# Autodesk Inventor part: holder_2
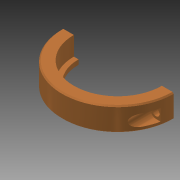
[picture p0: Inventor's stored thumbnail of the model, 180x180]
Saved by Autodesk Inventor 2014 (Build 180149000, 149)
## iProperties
Created: 2002-09
Part Number: holder_2
Document SubType Name: Modeling
Designer: ales
Density: 1 g/cm^3
Material: Generic
Appearance: Copper (Old/Polished)
ProtocolID: P00020918071214950
Protocol: P00020918071214950<@PID>[Object]<@EL>CADDescription=holder_2.ipt<@EL>[GroupMan]<@EL>UseUserDescription=1<@EL>UserDescription=holder_2.ipt<@EL>[Acad]<@EL>SmartPa
Control State: 0
Master: False
Checked Out: False
Shininess: 64.0
Length Units: 11269
Angle Units: 11279
Time Units: 11290
Mass Units: 11283
Length Display Precision: 3
Angle Display Precision: 2
Density: 0.0
Volumn: 0.0
Area: 0.0
PropertySet Name: Model Information
Author: PaulN
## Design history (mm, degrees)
sketch "Sketch1"
  geometry: L1 (24.298, 7.276)-(24.298, -8.724) reference; L2 (24.298, -8.724)-(28.298, -8.724) reference; L3 (28.298, -8.724)-(28.298, -12.724) reference; L4 (28.298, -12.724)-(14.298, -12.724) reference; L5 (14.298, 7.276)-(24.298, 7.276) reference; L6 (14.298, -12.724)-(14.298, 7.276); L7 (95.298, -12.724)-(28.298, -12.724) reference; L8 (61.798, -12.724)-(61.798, 7.654)
  constraints: 4 end point, 2 perpendicular, 1 midpoint, 1 parallel
revolve "Revolution1" sketch "Sketch1" stored, may be unused: angle "d0" = 180 deg
sketch "Sketch2"
  geometry: L1 (14, 20)-(14, 0) reference; L2 (9, 13)-(14, 13); L3 (9, 3)-(14, 3); L4 (4, 20)-(-71, 20) reference; L5 (-33.5, 20)-(-33.5, 4.517); L6 (-81, 0)-(-81, 20) reference; L7 (-76, 13)-(-81, 13); L8 (-76, 3)-(-81, 3); L9 (-81, 13)-(-81, 3); L10 (4, 20)-(14, 20) reference; C1 r 3 at (9, 8); C2 r 3 at (-76, 8); A1 r 5 centre (9, 8) between (9, 13) and (9, 3); A2 r 5 centre (-76, 8) between (-76, 3) and (-76, 13)
  constraints: 12 end point, 6 symmetric about line, 4 centre point, 4 point on circle, 2 coincident, 2 perpendicular, 2 point on line, 2 tangent, 1 collinear, 1 midpoint, 1 parallel, 4 other
  dimensions: "d1" = 10 diameter of A1; "d2" = 5 distance from line of L1 A1.centre; "d3" = 6 diameter of C1; "d11" = 12 distance from line of L10 A1.centre
extrude "Extrusion1" cut sketch "Sketch2" stored distance "d4" = 10; taper "d5" = 0 deg
workplane "Work Plane1"
workplane "Work Plane2"
extrude "Extrusion2" cut sketch "Sketch2" stored distance "d7" = 10; taper "d8" = 0 deg
chamfer "Chamfer1" distance "d9" = 1; stored, may be unused: second distance "d10" = 1, angle "d12" = 45 deg
body "Solid1"
node "Reference1"
node "Reference2"
node "Reference3"
node "Reference4"
node "Reference5"
node "Reference6"
